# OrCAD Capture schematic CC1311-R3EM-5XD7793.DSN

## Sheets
1 CC1311-R3EM-5XD7793: size A3; title: CC1311-R3EM-5XD7793; rev: A0
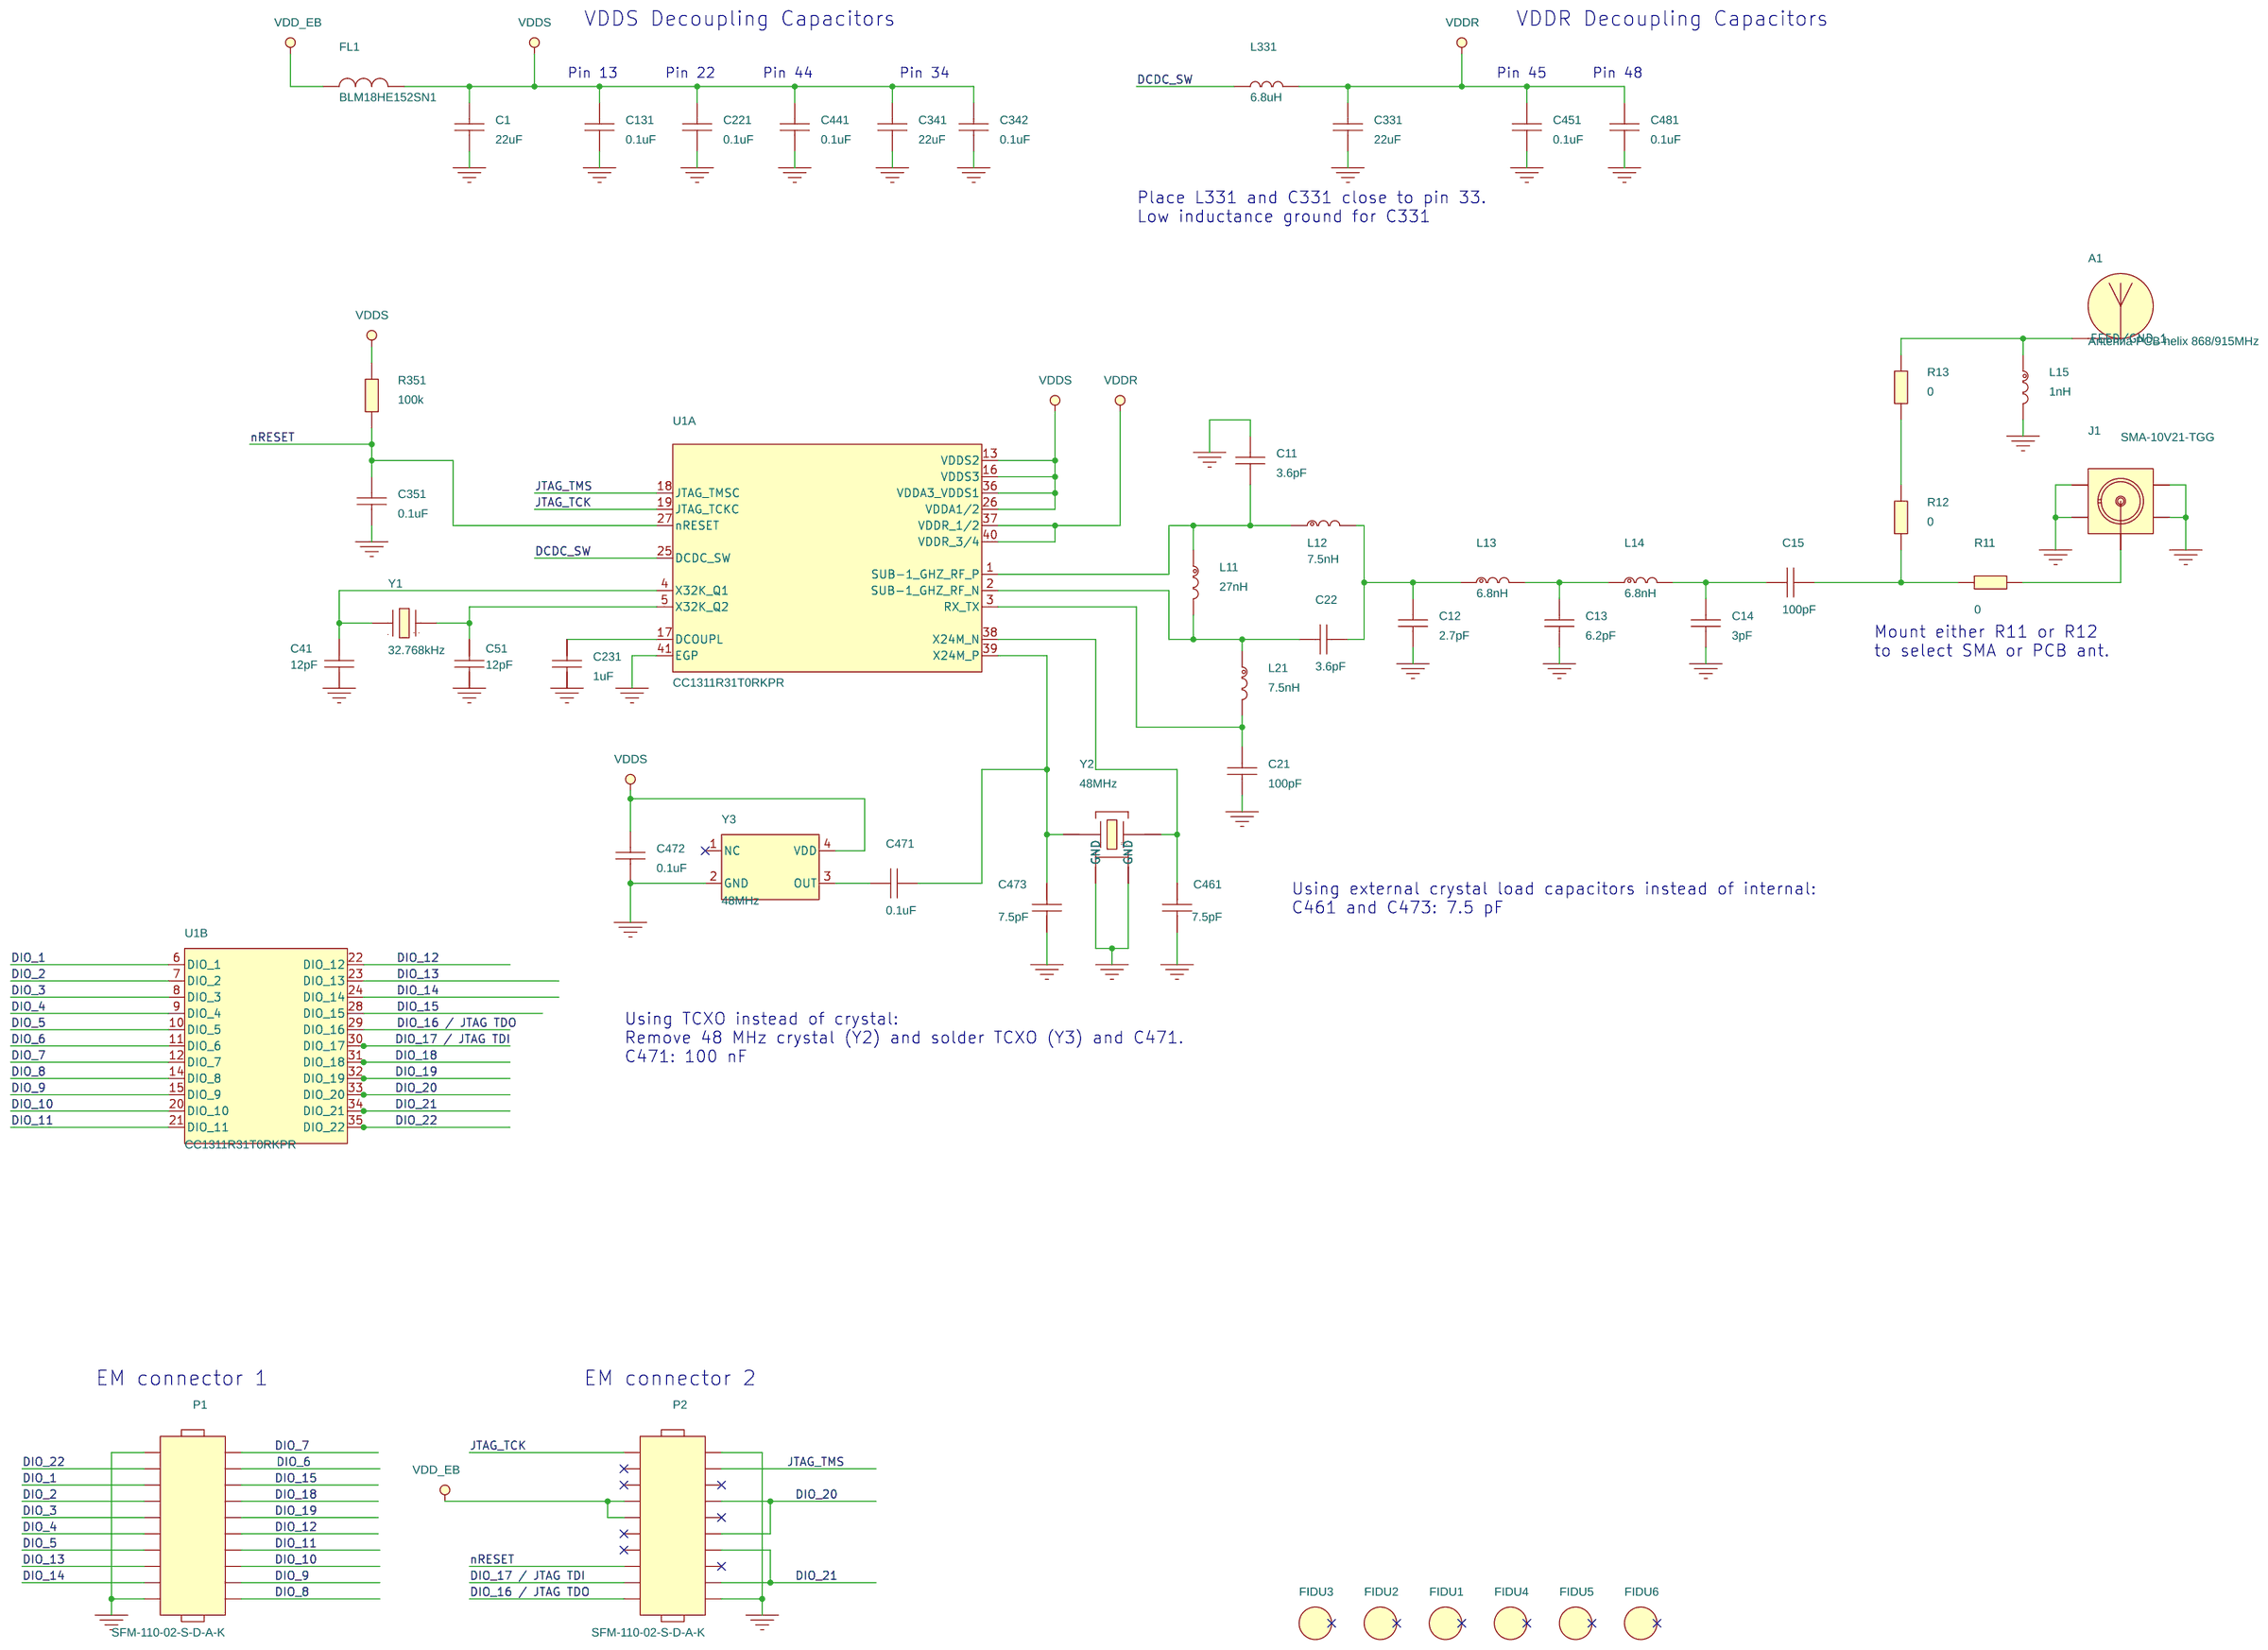
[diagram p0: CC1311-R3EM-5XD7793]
2 Revision
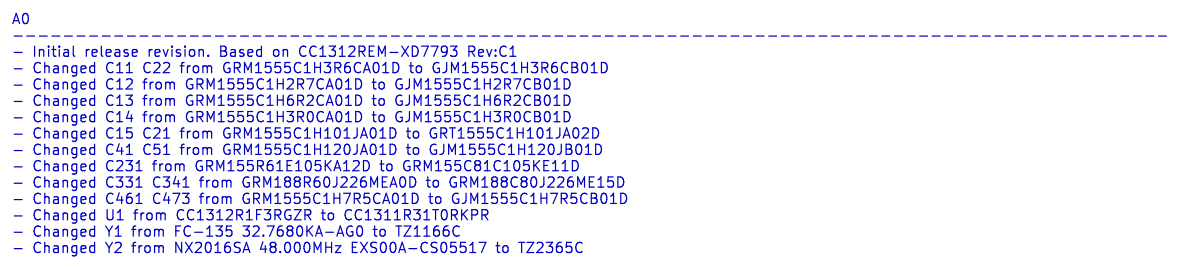
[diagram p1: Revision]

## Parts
A1  Antenna PCB helix 868/915MHz  [Antenna868_915MHz_A2N]
C1  22uF  [CAPC1608X100A2N]
C11  3.6pF  [CAPC1005X60B2N]
C12  2.7pF  [CAPC1005X60B2N]
C13  6.2pF  [CAPC1005X60B2N]
C14  3pF  [CAPC1005X60B2N]
C15  100pF  [CAPC1005X60B2N]
C21  100pF  [CAPC1005X60B2N]
C22  3.6pF  [CAPC1005X60B2N]
C41  12pF  [CAPC1005X60B2N]
C51  12pF  [CAPC1005X60B2N]
C131  0.1uF  [CAPC1005X60B2N]
C221  0.1uF  [CAPC1005X60B2N]
C231  1uF  [CAPC1005X60B2N]
C331  22uF  [CAPC1608X100A2N]
C341  22uF  [CAPC1608X100A2N]
C342  0.1uF  [CAPC1005X60B2N]
C351  0.1uF  [CAPC1005X60B2N]
C441  0.1uF  [CAPC1005X60B2N]
C451  0.1uF  [CAPC1005X60B2N]
C461  7.5pF  [CAPC1005X60B2N]
C471  0.1uF  [CAPC1005X60B2N]
C472  0.1uF  [CAPC1005X60B2N]
C473  7.5pF  [CAPC1005X60B2N]
C481  0.1uF  [CAPC1005X60B2N]
FIDU1  FIDU_1MM  [FID100X115B]
FIDU2  FIDU_1MM  [FID100X115B]
FIDU3  FIDU_1MM  [FID100X115B]
FIDU4  FIDU_1MM  [FID100X115B]
FIDU5  FIDU_1MM  [FID100X115B]
FIDU6  FIDU_1MM  [FID100X115B]
FL1  BLM18HE152SN1  [FIL_BLM18HE152SN1DN]
J1  SMA-10V21-TGG  [HUSTSAN_SMA10V21TGGAN]
L11  27nH  [INDC1005X60D2N]
L12  7.5nH  [INDC1005X60D2N]
L13  6.8nH  [INDC1005X60D2N]
L14  6.8nH  [INDC1005X60D2N]
L15  1nH  [INDC1005X60D2N]
L21  7.5nH  [INDC1005X60D2N]
L331  6.8uH  [INDC2012X150A2N]
P1  SFM-110-02-S-D-A-K  [SAMTEC_SFM11002AN]
P2  SFM-110-02-S-D-A-K  [SAMTEC_SFM11002AN]
R11  0  [RESC1005X40B2N]
R12  0  [RESC1005X40B2N]
R13  0  [RESC1005X40B2N]
R351  100k  [RESC1005X40B2N]
U1  CC1311R31T0RKPR  [QFNFC40P500X500X100-41A2N]  (sections A,B)
Y1  32.768kHz  [XTAL_TZ1166C_B2N]
Y2  48MHz  [OSCCC200X160X50-4A2N]
Y3  48MHz  [OSC_TG2016SBN_A2N]

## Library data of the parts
A1 = ANTENNA: ANTENNA, NON COMPONENT, PCB HELIX 868/915MHz, NOT APPLY; Additional Datasheet URL: N/A; AutoDoc File: http://notefied-dynamic-precision.com/DB/Apps/Desktop/Item/Object.aspx?id=87165; Budget Currency: N/A; Budget Price: N/A; CLASS: DISCRETE; Country of Origin: Missing Info; Datasheet URL: www.ti.com; Datasheet URL 1: N/A; Datasheet URL 2: www.ti.com; Definied Quality: COMMERCIAL; Esd Level: N/A; Exclusive for Customers: TEXAS INSTRUMENTS NORWAY; FPLIST: Antenna868_915MHz_A2N,Antenna868_915MHz_MIRROR_A2N,; LifeCycle Status: ACTIVE; MPN: ANTENNA PCB HELIX 868/915MHz; MPN Status: ACTIVE; MSL: N/A; MTBF: N/A; MTBF Standard: N/A; Manufacturer: TEXAS INSTRUMENTS; Mass: N/A; Max Oper Temp: N/A; Maximum Operating Temperature: N/A; Min Oper Temp: N/A; Minimum Operating Temperature: N/A; Mounting Type: Not Apply; NOTE Status: PREFERRED; NOTEfied URL: https://notefied-dynamic-precision.com/NOTEfiedWebInterface/part/show?partNumber=13-00397; Notes: Custom Item; Old Footprint: Antenna868_915MHz_A2N,Antenna868_915MHz_MIRROR_A2N; Packing Size: 2500; Packing Type: Tape & Reel; Part Number: 13-00397; Part Type: Mechanic|ANTENNA|NON COMPONENT; REACH/SVHC Compliance: Missing Info; REACH/SVHC Details: N/A; REACH/SVHC Source: N/A; REACH/SVHC Status: Missing Info; ROHS: Compliant; Revision: R019; RoHS Status: ROHS_COMPLIANT; Status: Released; Texas Part Status: Under Review; Type: Mechanic; Vendor: TEXAS INSTRUMENTS; Vendor Part Number: ANTENNA PCB HELIX 868/915MHz; Vendor Part Status: Active; WEIGHT: N/A
C1 = CAPACITOR: CAPACITOR, CERAMIC X6S, 22uF, 6.3V, -20%/+20%, -55DEGC/+105DEGC, 0603, SMD; ALT_SYMBOLS: CAPC1608X100A2L,CAPC1608X100A2M; Additional Datasheet URL: https://search.murata.co.jp/Ceramy/image/img/A01X/G101/ENG/GRM188C80J226ME15-02A.pdf; Budgetary Price: 0.07648 USD; CLASS: DISCRETE; Datasheet URL: https://www.murata.com/-/media/webrenewal/support/library/catalog/products/capacitor/mlcc/c02e.ashx; Dielectric Type: X6S; Lead Time: 15; Mass: 0.0091g; Maximum Operating Temperature: +105DEGC; Maximum Tolerance: +20%; Minimum Operating Temperature: -55DEGC; Minimum Tolerance: -20%; Mounting Type: SMD; NOTEfied URL: https://notefied-dynamic-precision.com/NOTEfiedWebInterface/part/show?partNumber=02-09737; PCB Package: 0603; Packing Size: 4000; Packing Type: Tape & Reel; Part Number: 02-09737; Part Type: Capacitor|CERAMIC|0603|STANDARD; REACH/SVHC Compliance: Compliant; REACH/SVHC Details: SVHC List Version Jan 16, 2020; REACH/SVHC Source: REACH Declaration; REACH/SVHC Status: Unaffected; ROHS: Compliant; Rated Current: N/A; Rated Voltage: 6.3V; Revision: R002; Status: Released; Texas Part Status: Under Review; Type: Capacitor; Vendor: MURATA; Vendor Part Number: GRM188C80J226ME15D; Vendor Part Status: Active
C11 C22 = CAPACITOR: CAPACITOR, CERAMIC C0G/NP0, 3.6pF, 50V, -0.25pF/+0.25pF, -55DEGC/+125DEGC, 0402, SMD; Additional Datasheet URL: https://search.murata.co.jp/Ceramy/image/img/A01X/G101/ENG/GJM1555C1H3R6CB01-01.pdf; Datasheet URL: https://www.murata.com/-/media/webrenewal/support/library/catalog/products/capacitor/mlcc/c02e.ashx; Dielectric Type: C0G/NP0; Mass: 0.0016g; Maximum Operating Temperature: +125DEGC; Maximum Tolerance: +0.25pF; Minimum Operating Temperature: -55DEGC; Minimum Tolerance: -0.25pF; Mounting Type: SMD; NOTEfied URL: https://notefied-dynamic-precision.com/NOTEfiedWebInterface/part/show?partNumber=02-09714; PCB Package: 0402; Packing Size: 10000; Packing Type: Tape & Reel; Part Number: 02-09714; Part Type: Capacitor|CERAMIC|0402|STANDARD; REACH/SVHC Compliance: Compliant; REACH/SVHC Details: SVHC List Version Jan 16, 2020; REACH/SVHC Source: REACH Declaration; REACH/SVHC Status: Unaffected; ROHS: Compliant; Rated Voltage: 50V; Revision: R003; Status: Released; Texas Part Status: Under Review; Type: Capacitor; Vendor: MURATA; Vendor Part Number: GJM1555C1H3R6CB01D; Vendor Part Status: Active
C12 = CAPACITOR: CAPACITOR, CERAMIC C0G/NP0, 2.7pF, 50V, -0.25pF/+0.25pF, -55DEGC/+125DEGC, 0402, SMD; Additional Datasheet URL: https://search.murata.co.jp/Ceramy/image/img/A01X/G101/ENG/GJM1555C1H2R7CB01-01.pdf; Datasheet URL: https://www.murata.com/-/media/webrenewal/support/library/catalog/products/capacitor/mlcc/c02e.ashx; Dielectric Type: C0G/NP0; Mass: 0.0016g; Maximum Operating Temperature: +125DEGC; Maximum Tolerance: +0.25pF; Minimum Operating Temperature: -55DEGC; Minimum Tolerance: -0.25pF; Mounting Type: SMD; NOTEfied URL: https://notefied-dynamic-precision.com/NOTEfiedWebInterface/part/show?partNumber=02-09712; PCB Package: 0402; Packing Size: 10000; Packing Type: Tape & Reel; Part Number: 02-09712; Part Type: Capacitor|CERAMIC|0402|STANDARD; REACH/SVHC Compliance: Compliant; REACH/SVHC Details: SVHC List Version Jan 16, 2020; REACH/SVHC Source: REACH Declaration; REACH/SVHC Status: Unaffected; ROHS: Compliant; Rated Voltage: 50V; Revision: R003; Status: Released; Texas Part Status: Under Review; Type: Capacitor; Vendor: MURATA; Vendor Part Number: GJM1555C1H2R7CB01D; Vendor Part Status: Active
C13 = CAPACITOR: CAPACITOR, CERAMIC C0G/NP0, 6.2pF, 50V, -0.25pF/+0.25pF, -55DEGC/+125DEGC, 0402, SMD; Additional Datasheet URL: https://search.murata.co.jp/Ceramy/image/img/A01X/G101/ENG/GJM1555C1H6R2CB01-01.pdf; Datasheet URL: https://www.murata.com/-/media/webrenewal/support/library/catalog/products/capacitor/mlcc/c02e.ashx; Dielectric Type: C0G/NP0; Mass: 0.0016g; Maximum Operating Temperature: +125DEGC; Maximum Tolerance: +0.25pF; Minimum Operating Temperature: -55DEGC; Minimum Tolerance: -0.25pF; Mounting Type: SMD; NOTEfied URL: https://notefied-dynamic-precision.com/NOTEfiedWebInterface/part/show?partNumber=02-09717; PCB Package: 0402; Packing Size: 10000; Packing Type: Tape & Reel; Part Number: 02-09717; Part Type: Capacitor|CERAMIC|0402|STANDARD; REACH/SVHC Compliance: Compliant; REACH/SVHC Details: SVHC List Version Jan 16, 2020; REACH/SVHC Source: REACH Declaration; REACH/SVHC Status: Unaffected; ROHS: Compliant; Rated Voltage: 50V; Revision: R003; Status: Released; Texas Part Status: Under Review; Type: Capacitor; Vendor: MURATA; Vendor Part Number: GJM1555C1H6R2CB01D; Vendor Part Status: Active
C14 = CAPACITOR: CAPACITOR, CERAMIC C0G/NP0, 3pF, 50V, -0.25pF/+0.25pF, -55DEGC/+125DEGC, 0402, SMD; Additional Datasheet URL: https://search.murata.co.jp/Ceramy/image/img/A01X/G101/ENG/GJM1555C1H3R0CB01-01.pdf; Datasheet URL: https://www.murata.com/-/media/webrenewal/support/library/catalog/products/capacitor/mlcc/c02e.ashx; Dielectric Type: C0G/NP0; Mass: 0.0016g; Maximum Operating Temperature: +125DEGC; Maximum Tolerance: +0.25pF; Minimum Operating Temperature: -55DEGC; Minimum Tolerance: -0.25pF; Mounting Type: SMD; NOTEfied URL: https://notefied-dynamic-precision.com/NOTEfiedWebInterface/part/show?partNumber=02-09713; PCB Package: 0402; Packing Size: 10000; Packing Type: Tape & Reel; Part Number: 02-09713; Part Type: Capacitor|CERAMIC|0402|STANDARD; REACH/SVHC Compliance: Compliant; REACH/SVHC Details: SVHC List Version Jan 16, 2020; REACH/SVHC Source: REACH Declaration; REACH/SVHC Status: Unaffected; ROHS: Compliant; Rated Voltage: 50V; Revision: R003; Status: Released; Texas Part Status: Under Review; Type: Capacitor; Vendor: MURATA; Vendor Part Number: GJM1555C1H3R0CB01D; Vendor Part Status: Active
C15 C21 = CAPACITOR: CAPACITOR, CERAMIC C0G/NP0, 100pF, 50V, -5%/+5%, -55DEGC/+125DEGC, 0402, SMD; Additional Datasheet URL: https://search.murata.co.jp/Ceramy/image/img/A01X/G101/ENG/GRT1555C1H101JA02-01.pdf; Budgetary Price: 0.023 EUR; Datasheet URL: https://www.murata.com/-/media/webrenewal/support/library/catalog/products/capacitor/mlcc/c02e.ashx?la=en-gb; Dielectric Type: C0G/NP0; Lead Time: 19; Mass: 0.0016g; Maximum Operating Temperature: +125DEGC; Maximum Tolerance: +5%; Minimum Operating Temperature: -55DEGC; Minimum Tolerance: -5%; Mounting Type: SMD; NOTEfied URL: https://notefied-dynamic-precision.com/NOTEfiedWebInterface/part/show?partNumber=02-09727; PCB Package: 0402; Packing Size: 10000; Packing Type: Tape & Reel; Part Number: 02-09727; Part Type: Capacitor|CERAMIC|0402|STANDARD; REACH/SVHC Compliance: Compliant; REACH/SVHC Details: SVHC List Version Jan 16, 2020; REACH/SVHC Source: REACH Declaration; REACH/SVHC Status: Unaffected; ROHS: Compliant; Rated Voltage: 50V; Revision: R003; Status: Released; Texas Part Status: Under Review; Type: Capacitor; Vendor: MURATA; Vendor Part Number: GRT1555C1H101JA02D; Vendor Part Status: Active
C41 C51 = CAPACITOR: CAPACITOR, CERAMIC C0G/NP0, 12pF, 50V, -5%/+5%, -55DEGC/+125DEGC, 0402, SMD; Additional Datasheet URL: https://search.murata.co.jp/Ceramy/image/img/A01X/G101/ENG/GJM1555C1H120JB01-01.pdf; AutoDoc File: http://notefied-dynamic-precision.com/DB/Apps/Desktop/Item/Object.aspx?id=84867; Budget Currency: EUR; Budget Price: 0.006; Datasheet URL: https://www.murata.com/-/media/webrenewal/support/library/catalog/products/capacitor/mlcc/c02e.ashx; Datasheet URL 1: http://search.murata.co.jp/Ceramy/image/img/w_hinm/L0005E.pdf; Datasheet URL 2: http://psearch.murata.com/capacitor/product/GRM1555C1H120JA01%23.pdf; Definied Quality: INDUSTRIAL; Dielectric Type: C0G/NP0; Esd Level: N/A; MPN: GRM1555C1H120JA01D; MPN Status: ACTIVE; MSL: 1; MTBF: N/A; MTBF Standard: N/A; Manufacturer: MURATA; Mass: 0.0016g; Max Oper Temp: +125DEGC; Max TC: +30PPM/DEGC; Max Tol: +5%; Maximum Operating Temperature: +125DEGC; Maximum Tolerance: +5%; Min Oper Temp: -55DEGC; Min TC: -30PPM/DEGC; Min Tol: -5%; Minimum Operating Temperature: -55DEGC; Minimum Tolerance: -5%; Mounting Type: SMD; NOTE Status: PREFERRED; NOTEfied URL: https://notefied-dynamic-precision.com/NOTEfiedWebInterface/part/show?partNumber=02-09704; Old Footprint: CAPC1005X60N; PCB Package: 0402; Packing Size: 10000; Packing Type: Tape & Reel; Part Number: 02-09704; Part Type: Capacitor|CERAMIC|0402|STANDARD; REACH/SVHC Compliance: Compliant; REACH/SVHC Details: SVHC List Version Jan 16, 2020; REACH/SVHC Source: REACH Declaration; REACH/SVHC Status: Unaffected; ROHS: Compliant; Rated Voltage: 50V; Revision: R003; RoHS Status: ROHS_COMPLIANT; Rtd Voltage: 50V; Status: Released; Texas Part Status: Under Review; Type: Capacitor; Vendor: MURATA; Vendor Part Number: GJM1555C1H120JB01D; Vendor Part Status: Active; WEIGHT: 0.0016g
C131 C221 C342 C351 C441 C451 C471 C472 C481 = CAPACITOR: CAPACITOR, CERAMIC X7R, 0.1uF, 25V, -10%/+10%, -55DEGC/+125DEGC, 0402, SMD; Additional Datasheet URL: https://search.murata.co.jp/Ceramy/image/img/A01X/G101/ENG/GRM155R71E104KE14-01A.pdf; CLASS: DISCRETE; Datasheet URL: https://www.murata.com/~/media/webrenewal/support/library/catalog/products/capacitor/mlcc/c02e.ashx?la=en-gb; Dielectric Type: X7R; Mass: 0.0016g; Maximum Operating Temperature: +125DEGC; Maximum Tolerance: +10%; Minimum Operating Temperature: -55DEGC; Minimum Tolerance: -10%; Mounting Type: SMD; NOTEfied URL: https://notefied-dynamic-precision.com/NOTEfiedWebInterface/part/show?partNumber=02-07861; PCB Package: 0402; Packing Size: 10000; Packing Type: Tape & Reel; Part Number: 02-07861; Part Type: Capacitor|CERAMIC|0402|STANDARD; REACH/SVHC Compliance: Compliant; REACH/SVHC Details: SVHC List Version Jul 7, 2017; REACH/SVHC Source: REACH Declaration; REACH/SVHC Status: Unaffected; ROHS: Compliant; Rated Voltage: 25V; Revision: R014; Status: Released; Texas Part Status: Under Review; Type: Capacitor; Vendor: MURATA; Vendor Part Number: GRM155R71E104KE14D; Vendor Part Status: NRND
C231 = CAPACITOR: CAPACITOR, CERAMIC X6S, 1uF, 16V, -10%/+10%, -55DEGC/+105DEGC, 0402, SMD; Additional Datasheet URL: https://search.murata.co.jp/Ceramy/image/img/A01X/G101/ENG/GRM155C81C105KE11-01A.pdf; Datasheet URL: https://www.murata.com/-/media/webrenewal/support/library/catalog/products/capacitor/mlcc/c02e.ashx; Dielectric Type: X6S; Mass: 0.0016g; Maximum Operating Temperature: +105DEGC; Maximum Tolerance: +10%; Minimum Operating Temperature: -55DEGC; Minimum Tolerance: -10%; Mounting Type: SMD; NOTEfied URL: https://notefied-dynamic-precision.com/NOTEfiedWebInterface/part/show?partNumber=02-09724; PCB Package: 0402; Packing Size: 10000; Packing Type: Tape & Reel; Part Number: 02-09724; Part Type: Capacitor|CERAMIC|0402|STANDARD; REACH/SVHC Compliance: Compliant; REACH/SVHC Details: SVHC List Version Jan 16, 2020; REACH/SVHC Source: REACH Declaration; REACH/SVHC Status: Unaffected; ROHS: Compliant; Rated Voltage: 16V; Revision: R003; Status: Released; Texas Part Status: Under Review; Type: Capacitor; Vendor: MURATA; Vendor Part Number: GRM155C81C105KE11D; Vendor Part Status: Active
C331 C341 = CAPACITOR: CAPACITOR, CERAMIC X6S, 22uF, 6.3V, -20%/+20%, -55DEGC/+105DEGC, 0603, SMD; ALT_SYMBOLS: CAPC1608X100A2L,CAPC1608X100A2M; Additional Datasheet URL: https://search.murata.co.jp/Ceramy/image/img/A01X/G101/ENG/GRM188C80J226ME15-02A.pdf; Budgetary Price: 0.07648 USD; Datasheet URL: https://www.murata.com/-/media/webrenewal/support/library/catalog/products/capacitor/mlcc/c02e.ashx; Dielectric Type: X6S; Lead Time: 15; Mass: 0.0091g; Maximum Operating Temperature: +105DEGC; Maximum Tolerance: +20%; Minimum Operating Temperature: -55DEGC; Minimum Tolerance: -20%; Mounting Type: SMD; NOTEfied URL: https://notefied-dynamic-precision.com/NOTEfiedWebInterface/part/show?partNumber=02-09737; PCB Package: 0603; Packing Size: 4000; Packing Type: Tape & Reel; Part Number: 02-09737; Part Type: Capacitor|CERAMIC|0603|STANDARD; REACH/SVHC Compliance: Compliant; REACH/SVHC Details: SVHC List Version Jan 16, 2020; REACH/SVHC Source: REACH Declaration; REACH/SVHC Status: Unaffected; ROHS: Compliant; Rated Current: N/A; Rated Voltage: 6.3V; Revision: R002; Status: Released; Texas Part Status: Under Review; Type: Capacitor; Vendor: MURATA; Vendor Part Number: GRM188C80J226ME15D; Vendor Part Status: Active
C461 C473 = CAPACITOR: CAPACITOR, CERAMIC C0G/NP0, 7.5pF, 50V, -0.25pF/+0.25pF, -55DEGC/+125DEGC, 0402, SMD; Additional Datasheet URL: https://search.murata.co.jp/Ceramy/image/img/A01X/G101/ENG/GJM1555C1H7R5CB01-01.pdf; Datasheet URL: https://www.murata.com/-/media/webrenewal/support/library/catalog/products/capacitor/mlcc/c02e.ashx; Dielectric Type: C0G/NP0; Mass: 0.0016g; Maximum Operating Temperature: +125DEGC; Maximum Tolerance: +0.25pF; Minimum Operating Temperature: -55DEGC; Minimum Tolerance: -0.25pF; Mounting Type: SMD; NOTEfied URL: https://notefied-dynamic-precision.com/NOTEfiedWebInterface/part/show?partNumber=02-09718; PCB Package: 0402; Packing Size: 10000; Packing Type: Tape & Reel; Part Number: 02-09718; Part Type: Capacitor|CERAMIC|0402|STANDARD; REACH/SVHC Compliance: Compliant; REACH/SVHC Details: SVHC List Version Jan 16, 2020; REACH/SVHC Source: REACH Declaration; REACH/SVHC Status: Unaffected; ROHS: Compliant; Rated Voltage: 50V; Revision: R003; Status: Released; Texas Part Status: Under Review; Type: Capacitor; Vendor: MURATA; Vendor Part Number: GJM1555C1H7R5CB01D; Vendor Part Status: Active
FIDU1-FIDU6 = FIDMARK: NON COMPONENT, FIDUCIAL MARK, ROUND 1mm, SMD; Additional Datasheet URL: N/A; AutoDoc File: http://notefied-dynamic-precision.com/DB/Apps/Desktop/Item/Object.aspx?id=74548; CLASS: IO; Country of Origin: Missing Info; Datasheet URL: N/A; Mass: N/A; Mounting Type: SMD; NOTEfied URL: https://notefied-dynamic-precision.com/NOTEfiedWebInterface/part/show?partNumber=19-00111; Old Footprint: FID100X115; Packing Size: N/A; Packing Type: Missing Info; Part Number: 19-00111; Part Type: Non Component|FIDUCIAL; ROHS: Compliant; Revision: R015; Status: Released; Type: Non Component; Vendor: NON_COMPONENT; Vendor Part Number: FIDUCIAL_1mm; Vendor Part Status: Active
FL1 = FILTER_2PIN: FILTER, EMI, FERRITE BEAD, 1500@100MHz, -25%/+25%, -55DEGC/+125DEGC, 0603, SMD; ALT_SYMBOLS: FIL_BLM18HE152SN1DL,FIL_BLM18HE152SN1DM; Additional Datasheet URL: https://www.murata.com/en-eu/products/productdata/8796741599262/ENFA0004.pdf?1441769419000; Budgetary Price: 0.065 EUR; Country of Origin: Japan,Singapore,Thailand; Datasheet URL: https://www.murata.com/~/media/webrenewal/support/library/catalog/products/emc/emifil/c31e.ashx; Frequency: 100MHz; Impedance: 1500; Inductance: N/A; Lead Time: 9; Mass: 0.006g; Maximum Operating Temperature: +125DEGC; Maximum Tolerance: +25%; Minimum Operating Temperature: -55DEGC; Minimum Tolerance: -25%; Mounting Type: SMD; NOTEfied URL: https://notefied-dynamic-precision.com/NOTEfiedWebInterface/part/show?partNumber=04-00470; PCB Package: 0603; Packing Size: 4000; Packing Type: Tape & Reel; Part Number: 04-00470; Part Type: Filter|EMI|FERRITE BEAD|0603; REACH/SVHC Compliance: Compliant; REACH/SVHC Details: SVHC List Version Jul 7, 2017; REACH/SVHC Source: REACH Declaration; REACH/SVHC Status: Unaffected; ROHS: Compliant; Rated Current: 0.5A; Rated Voltage: N/A; Revision: R015; Status: Released; Texas Part Status: Under Review; Type: Filter; Vendor: MURATA; Vendor Part Number: BLM18HE152SN1D; Vendor Part Status: Active
J1 = CONN_COAX_1+4: CONNECTOR, COAX, RF, FEMALE, STRAIGHT, 1 PIN, SMD; ALT_SYMBOLS: HUSTSAN_SMA10V21TGGL,HUSTSAN_SMA10V21TGGM; Additional Datasheet URL: http://www.hustsan.com.tw/cgi-bin/productfn/pdt_detail_lst.pl?ProdID=143; AutoDoc File: http://notefied-dynamic-precision.com/DB/Apps/Desktop/Item/Object.aspx?id=84956; Budget Currency: USD; Budget Price: 1.21; CLASS: IO; Country of Origin: Taiwan; Datasheet URL: http://www.hustsan.com.tw/uploaddir/product/SMA-10V21.pdf; Datasheet URL 1: http://www.hustsan.com.tw/uploaddir/product/SMA-10V21.pdf; Datasheet URL 2: http://www.hustsan.com.tw/uploaddir/product/SMA-10V21.pdf; FPLIST: HUSTSAN_SMA10V21TGGAN,HUSTSAN_SMA10V21TGGN; MPN Status: ACTIVE; MSL: N/A; Manufacturer: HUS-TSAN; Mass: N/A; Mounting Type: SMD; NOTE Status: PREFERRED; NOTEfied URL: https://notefied-dynamic-precision.com/NOTEfiedWebInterface/part/show?partNumber=06-02188; No Of Pos: 1; Number of Positions: 1; Old Footprint: HUSTSAN_SMA10V21TGGAN,HUSTSAN_SMA10V21TGGN; Packing Size: 350; Packing Type: Tape & Reel; Part Number: 06-02188; Part Type: Connector|COAX|RF; REACH/SVHC Compliance: Compliant; REACH/SVHC Details: SVHC List Version Jun 20, 2016; REACH/SVHC Source: REACH Declaration; REACH/SVHC Status: Unaffected; ROHS: Compliant; Revision: R014; RoHS Status: N/A; Status: Released; Texas Part Status: Under Review; Type: Connector; Vendor: HUS-TSAN; Vendor Part Status: Active; WEIGHT: N/A
L11 = INDUCTOR_HOR_1_2: INDUCTOR, RF, CHIP, NON-MAGNETIC CORE, 27nH, -5%/+5%, 0.3A, -55DEGC/+125DEGC, 0402, SMD; Additional Datasheet URL: https://search.murata.co.jp/Ceramy/image/img/P02/JELF243B-0010.pdf; Budgetary Price: 0.03 EUR; Country of Origin: Japan,Singapore; Datasheet URL: https://www.murata.com/~/media/webrenewal/support/library/catalog/products/inductor/chip/o05e.ashx?la=en-gb; Exclusive for Customers: TEXAS INSTRUMENTS NORWAY; Frequency: 1700MHz; Lead Time: 9; Mass: 0.001g; Maximum Operating Temperature: +125DEGC; Maximum Tolerance: +5%; Minimum Operating Temperature: -55DEGC; Minimum Tolerance: -5%; Mounting Type: SMD; NOTEfied URL: https://notefied-dynamic-precision.com/NOTEfiedWebInterface/part/show?partNumber=03-07528; Notes: Standard item: Duplicate Reason: custom footprint for TEXAS INSTRUMENTS NORWAY.; PCB Package: 0402; Packing Size: 10000; Packing Type: Tape & Reel; Part Number: 03-07528; Part Type: Inductor|RF|CHIP|0402; REACH/SVHC Compliance: Compliant; REACH/SVHC Details: SVHC List Version Jul 7, 2017; REACH/SVHC Source: REACH Declaration; REACH/SVHC Status: Unaffected; ROHS: Compliant; Resistance: 0.46; Revision: R018; Status: Released; Texas Part Status: Under Review; Type: Inductor; Vendor: MURATA; Vendor Part Number: LQG15HS27NJ02D; Vendor Part Status: Active
L12 L21 = INDUCTOR_HOR_1_2: INDUCTOR, RF, CHIP, NON-MAGNETIC CORE, 7.5nH, -5%/+5%, 0.3A, -55DEGC/+125DEGC, 0402, SMD; Additional Datasheet URL: https://search.murata.co.jp/Ceramy/image/img/P02/JELF243B-0010.pdf; Budgetary Price: 0.03 EUR; Country of Origin: Missing Info; Datasheet URL: https://www.murata.com/~/media/webrenewal/support/library/catalog/products/inductor/chip/o05e.ashx?la=en-gb; Frequency: 4.2GHz; Lead Time: 10; Mass: 0.001g; Maximum Operating Temperature: +125DEGC; Maximum Tolerance: +5%; Minimum Operating Temperature: -55DEGC; Minimum Tolerance: -5%; Mounting Type: SMD; NOTEfied URL: https://notefied-dynamic-precision.com/NOTEfiedWebInterface/part/show?partNumber=03-07022; PCB Package: 0402; Packing Size: 10000; Packing Type: Tape & Reel; Part Number: 03-07022; Part Type: Inductor|RF|CHIP|0402; REACH/SVHC Compliance: Compliant; REACH/SVHC Details: SVHC List Version Jul 7, 2017; REACH/SVHC Source: REACH Declaration; REACH/SVHC Status: Unaffected; ROHS: Compliant; Resistance: 0.24; Revision: R017; Status: Released; Texas Part Status: Under Review; Type: Inductor; Vendor: MURATA; Vendor Part Number: LQG15HS7N5J02D; Vendor Part Status: Active
L13 L14 = INDUCTOR_HOR_1_2: INDUCTOR, RF, CHIP, NON-MAGNETIC CORE, 6.8nH, -5%/+5%, 0.3A, -55DEGC/+125DEGC, 0402, SMD; Additional Datasheet URL: https://search.murata.co.jp/Ceramy/image/img/P02/JELF243B-0010.pdf; Budgetary Price: 0.03 EUR; Country of Origin: Japan,Singapore; Datasheet URL: https://www.murata.com/~/media/webrenewal/support/library/catalog/products/inductor/chip/o05e.ashx?la=en-gb; Exclusive for Customers: TEXAS INSTRUMENTS NORWAY; Frequency: 4.5GHz; Lead Time: 9; Mass: 0.001g; Maximum Operating Temperature: +125DEGC; Maximum Tolerance: +5%; Minimum Operating Temperature: -55DEGC; Minimum Tolerance: -5%; Mounting Type: SMD; NOTEfied URL: https://notefied-dynamic-precision.com/NOTEfiedWebInterface/part/show?partNumber=03-07532; Notes: Standard item: Duplicate Reason: custom footprint for TEXAS INSTRUMENTS NORWAY.; PCB Package: 0402; Packing Size: 10000; Packing Type: Tape & Reel; Part Number: 03-07532; Part Type: Inductor|RF|CHIP|0402; REACH/SVHC Compliance: Compliant; REACH/SVHC Details: SVHC List Version Jul 7, 2017; REACH/SVHC Source: REACH Declaration; REACH/SVHC Status: Unaffected; ROHS: Compliant; Resistance: 0.24; Revision: R018; Status: Released; Texas Part Status: Under Review; Type: Inductor; Vendor: MURATA; Vendor Part Number: LQG15HS6N8J02D; Vendor Part Status: Active
L15 = INDUCTOR_HOR_1_2: INDUCTOR, RF, CHIP, NON-MAGNETIC CORE, 1nH, -0.3nH/+0.3nH, 0.3A, -55DEGC/+125DEGC, 0402, SMD; ALT_SYMBOLS: INDC1005X60C2L,INDC1005X60C2M; Additional Datasheet URL: https://search.murata.co.jp/Ceramy/image/img/P02/JELF243B-0010.pdf; Budgetary Price: 0.031 EUR; Country of Origin: Japan,Singapore; Datasheet URL: https://www.murata.com/~/media/webrenewal/support/library/catalog/products/inductor/chip/o05e.ashx?la=en-gb; Frequency: 10GHz; Lead Time: 9; Mass: 0.001g; Maximum Operating Temperature: +125DEGC; Maximum Tolerance: +0.3nH; Minimum Operating Temperature: -55DEGC; Minimum Tolerance: -0.3nH; Mounting Type: SMD; NOTEfied URL: https://notefied-dynamic-precision.com/NOTEfiedWebInterface/part/show?partNumber=03-06607; PCB Package: 0402; Packing Size: 10000; Packing Type: Tape & Reel; Part Number: 03-06607; Part Type: Inductor|RF|CHIP|0402; REACH/SVHC Compliance: Compliant; REACH/SVHC Details: SVHC List Version Jul 7, 2017; REACH/SVHC Source: REACH Declaration; REACH/SVHC Status: Unaffected; ROHS: Compliant; Resistance: 0.07; Revision: R016; Status: Released; Texas Part Status: Under Review; Type: Inductor; Vendor: MURATA; Vendor Part Number: LQG15HS1N0S02D; Vendor Part Status: Active
L331 = INDUCTOR: INDUCTOR, STANDARD, FERRITE CORE, 6.8uH, -20%/+20%, 0.11A, -55DEGC/+125DEGC, 0805, SMD; ALT_SYMBOLS: INDC2012X150A2L,INDC2012X150A2M; Additional Datasheet URL: https://product.tdk.com/en/search/inductor/inductor/smd/info?part_no=MLZ2012N6R8LT000; Budgetary Price: 0.045 USD; Country of Origin: Missing Info; Datasheet URL: http://product.tdk.com/info/en/catalog/datasheets/inductor_commercial_decoupling_mlz2012_en.pdf; Lead Time: 10; Mass: 0.01g; Maximum Operating Temperature: +125DEGC; Maximum Tolerance: +20%; Minimum Operating Temperature: -55DEGC; Minimum Tolerance: -20%; Mounting Type: SMD; NOTEfied URL: https://notefied-dynamic-precision.com/NOTEfiedWebInterface/part/show?partNumber=03-07266; PCB Package: 0805; Packing Size: 4000; Packing Type: Tape & Reel; Part Number: 03-07266; Part Type: Inductor|STANDARD|CHIP|0805; REACH/SVHC Compliance: Compliant; REACH/SVHC Details: SVHC List Version Jan 12, 2017; REACH/SVHC Source: REACH Declaration; REACH/SVHC Status: Unaffected; ROHS: Compliant; Resistance: 0.25; Revision: R014; Status: Released; Texas Part Status: Under Review; Type: Inductor; Vendor: TDK; Vendor Part Number: MLZ2012N6R8LT000; Vendor Part Status: Active
P1 P2 = CONN_HEADER_2X10_P_S: CONNECTOR, HEADER, FEMALE, STRAIGHT, 2 ROWS, 20 PINS, PITCH 1.27mm, SMD; ALT_SYMBOLS: SAMTEC_SFM11002AL,SAMTEC_SFM11002AM; Additional Datasheet URL: http://suddendocs.samtec.com/prints/sfm-1xx-xx-xxx-d-xxx-mkt.pdf; Alt IPC Footprints: SAMTEC_SFM11002AL,SAMTEC_SFM11002AM; AutoDoc File: https://notefied-dynamic-precision.com/NotefiedWebServices/AutoDocs.aspx?itemid=85603; Budgetary Price: 5.3504 USD; CLASS: IO; Country of Origin: China,Costa Rica,Malaysia,Singapore,United States; Datasheet URL: http://suddendocs.samtec.com/catalog_english/sfm.pdf; Datasheet URL 1: http://www.samtec.com/ProductInformation/TechnicalSpecifications/CatalogPages.aspx?series=SFM; Datasheet URL 2: http://www.samtec.com/documents/webfiles/cpdf/SFM-1XX-XX-XX-S-XX-MKT1.pdf; Lead Time: 4; MPN: SFM-110-02-SM-D-A-K-TR; MPN Status: ACTIVE; Manufacturer: SAMTEC; Mass: 0.30875g; Max Oper Temp: +125DEGC; Maximum Operating Temperature: +125DEGC; Min Oper Temp: -55DEGC; Minimum Operating Temperature: -55DEGC; Mounting Type: SMD; NOTE Status: PREFERRED; NOTEfied URL: https://notefied-dynamic-precision.com/NOTEfiedWebInterface/part/show?partNumber=06-02251; No Of Pos: 20; No Of Rows: 2; Number of Positions: 20; Number of Rows: 2; Packing Size: 725; Packing Type: Tape & Reel; Part Number: 06-02251; Part Type: Connector|HEADER|STANDARD; Pitch: 1.27mm; REACH/SVHC Compliance: Compliant; REACH/SVHC Details: SVHC List Version Jan 12, 2017; REACH/SVHC Source: Material Declaration; REACH/SVHC Status: Unaffected; ROHS: Compliant; Revision: R013; RoHS Status: ROHS_COMPLIANT; Status: Released; Texas Part Status: Under Review; Type: Connector; Vendor: SAMTEC; Vendor Part Number: SFM-110-02-SM-D-A-K-TR; Vendor Part Status: Active
R11-R13 = RESISTOR: RESISTOR, THICK FILM, 0, 0R/+0.02R, 0.063W, 1.5A, -55DEGC/+155DEGC, 0402, SMD; Additional Datasheet URL: N/A; Budgetary Price: 0.007 EUR; Country of Origin: Israel; Datasheet URL: http://www.vishay.com/docs/20035/dcrcwe3.pdf; Exclusive for Customers: TEXAS INSTRUMENTS NORWAY; Lead Time: 14; Mass: 0.0006152g; Maximum Operating Temperature: +155DEGC; Maximum Temperature Coefficient: N/A; Maximum Tolerance: +0.02R; Minimum Operating Temperature: -55DEGC; Minimum Temperature Coeficient: N/A; Minimum Tolerance: 0R; Mounting Type: SMD; NOTEfied URL: https://notefied-dynamic-precision.com/NOTEfiedWebInterface/part/show?partNumber=01-22495; Notes: Standard item: Duplicate Reason: custom footprint for TEXAS INSTRUMENTS NORWAY.; PCB Package: 0402; Packing Size: 10000; Packing Type: Tape & Reel; Part Number: 01-22495; Part Type: Resistor|0402|JUMPER; REACH/SVHC Compliance: Compliant; REACH/SVHC Details: SVHC List Version Jul 07, 2017; REACH/SVHC Source: REACH Declaration; REACH/SVHC Status: Unaffected; ROHS: Exempt; Rated Current: 1.5A; Rated Power: 0.063W; Rated Voltage: N/A; Resistor Type: THICK FILM; Revision: R021; Status: Released; Texas Part Status: Under Review; Type: Resistor; Vendor: VISHAY; Vendor Part Number: CRCW04020000Z0ED; Vendor Part Status: Active
R351 = RESISTOR: RESISTOR, THICK FILM, 100k, -5%/+5%, 0.063W, 50V, -55DEGC/+155DEGC, 0402, SMD; Additional Datasheet URL: N/A; Budgetary Price: 0.014 EUR; Country of Origin: United States; Datasheet URL: https://www.vishay.com/docs/20035/dcrcwe3.pdf; Exclusive for Customers: TEXAS INSTRUMENTS NORWAY; Lead Time: 18; Mass: 0.00065g; Maximum Operating Temperature: +155DEGC; Maximum Temperature Coefficient: +200PPM/DEGC; Maximum Tolerance: +5%; Minimum Operating Temperature: -55DEGC; Minimum Temperature Coeficient: -200PPM/DEGC; Minimum Tolerance: -5%; Mounting Type: SMD; NOTEfied URL: https://notefied-dynamic-precision.com/NOTEfiedWebInterface/part/show?partNumber=01-22492; Notes: Standard item: Duplicate Reason: custom footprint for TEXAS INSTRUMENTS NORWAY.; PCB Package: 0402; Packing Size: 10000; Packing Type: Tape & Reel; Part Number: 01-22492; Part Type: Resistor|0402|STANDARD; REACH/SVHC Compliance: Compliant; REACH/SVHC Details: SVHC List Version Jun 20, 2016; REACH/SVHC Source: Material Declaration; REACH/SVHC Status: Unaffected; ROHS: Exempt; Rated Current: N/A; Rated Power: 0.063W; Rated Voltage: 50V; Resistor Type: THICK FILM; Revision: R014; Status: Released; Texas Part Status: Under Review; Type: Resistor; Vendor: VISHAY; Vendor Part Number: CRCW0402100KJNED; Vendor Part Status: Active
U1 = IC_RF_CC1311R1F32TRKPR_VQFN40: IC, MICROCONTROLLER, TEXAS INSTRUMENTS, CC1311R SIMPLE LINK HIGH-REFORMANCE SUB-1GHz WIRELESS MCU, 1.8V TO 3.8V, VQFN40-EP, SMD; ALT_SYMBOLS: QFNFC40P500X500X100-41A2L,QFNFC40P500X500X100-41A2M; Additional Datasheet URL: N/A; Datasheet URL: https://www.ti.com/; Exclusive for Customers: TEXAS INSTRUMENTS NORWAY; Frequency: 48MHz; Mass: N/A; Maximum Operating Temperature: +105DEGC; Minimum Operating Temperature: -40DEGC; Mounting Type: SMD; NOTEfied URL: https://notefied-dynamic-precision.com/NOTEfiedWebInterface/part/show?partNumber=18-36302; Notes: Preliminary item, please check if it apperas on the website.; PCB Package: VQFN40-EP; Packing Size: N/A; Packing Type: Missing Info; Part Number: 18-36302; Part Type: IC|MICROCONTROLLER|TEXAS INSTRUMENTS; REACH/SVHC Compliance: Missing Info; REACH/SVHC Details: N/A; REACH/SVHC Source: N/A; REACH/SVHC Status: Missing Info; ROHS: Compliant; Rated Voltage: 1.8V TO 3.8V; Revision: R002; Status: Released; Texas Part Status: Under Review; Type: IC; Vendor: TEXAS INSTRUMENTS; Vendor Part Status: Preliminary
Y1 = XTAL: CRYSTAL, RESONATOR, 32.768kHz, -40DEGC/+125DEGC, SMD; ALT_SYMBOLS: XTAL_TZ1166C_B2L,XTAL_TZ1166C_B2M; Additional Datasheet URL: N/A; Capacitance: 7pF; Datasheet URL: https://www.taisaw.com/en/product.php?pc=7; Exclusive for Customers: TEXAS INSTRUMENTS NORWAY; Mass: N/A; Maximum Operating Temperature: +125DEGC; Maximum Stability: N/A; Maximum Tolerance: +20PPM; Minimum Operating Temperature: -40DEGC; Minimum Stability: N/A; Minimum Tolerance: -20PPM; Mounting Type: SMD; NOTEfied URL: https://notefied-dynamic-precision.com/NOTEfiedWebInterface/part/show?partNumber=12-01495; Notes: Non-standard part/non-catalogue part. Created on the basis of documentation provided by the customer (Texas Instruments).; Packing Size: 3000; Packing Type: Tape & Reel; Part Number: 12-01495; Part Type: Crystal|RESONATOR; REACH/SVHC Compliance: Missing Info; REACH/SVHC Details: N/A; REACH/SVHC Source: N/A; REACH/SVHC Status: Missing Info; ROHS: Compliant; Revision: R003; Status: Released; Texas Part Status: Under Review; Type: Crystal; Vendor: TAI-SAW; Vendor Part Number: TZ1166C; Vendor Part Status: Active
Y2 = XTAL_4_V3: CRYSTAL, RESONATOR, 48MHz, -16PPM/+16PPM, -40DEGC/+105DEGC, SMD; ALT_SYMBOLS: OSCCC200X160X50-4A2L,OSCCC200X160X50-4A2M; Additional Datasheet URL: N/A; Capacitance: 7pF; Datasheet URL: https://www.taisaw.com/en/product.php?pc=7; Exclusive for Customers: TEXAS INSTRUMENTS NORWAY; Mass: 0.0057g; Maximum Operating Temperature: +105DEGC; Maximum Stability: +16PPM; Maximum Tolerance: +8PPM; Minimum Operating Temperature: -40DEGC; Minimum Stability: -16PPM; Minimum Tolerance: -8PPM; Mounting Type: SMD; NOTEfied URL: https://notefied-dynamic-precision.com/NOTEfiedWebInterface/part/show?partNumber=12-01494; Notes: Non-standard part/non-catalogue part. Created on the basis of documentation provided by the customer (Texas Instruments).; Packing Size: 3000; Packing Type: Tape & Reel; Part Number: 12-01494; Part Type: Crystal|RESONATOR; REACH/SVHC Compliance: Missing Info; REACH/SVHC Details: N/A; REACH/SVHC Source: N/A; REACH/SVHC Status: Missing Info; ROHS: Compliant; Revision: R002; Status: Released; Texas Part Status: Under Review; Type: Crystal; Vendor: TAI-SAW; Vendor Part Number: TZ2365C; Vendor Part Status: Active
Y3 = XTAL_GEN: CRYSTAL, OSCILLATOR, TCXO, 48MHz, -0.5PPM/+0.5PPM, 1.8V TO 3.3V, -40DEGC/+85DEGC, SMD; ALT_SYMBOLS: OSC_TG2016SBN_A2L,OSC_TG2016SBN_A2M; Additional Datasheet URL: http://www5.epsondevice.com/en/products/tcxo/tg2016sbn.html; Datasheet URL: https://support.epson.biz/td/api/doc_check.php?dl=brief_TG2016SBN&lang=en; Maximum Operating Temperature: +85DEGC; Maximum Stability: +0.5PPM; Minimum Operating Temperature: -40DEGC; Minimum Stability: -0.5PPM; Mounting Type: SMD; NOTEfied URL: https://notefied-dynamic-precision.com/NOTEfiedWebInterface/part/show?partNumber=12-01262; Part Number: 12-01262; Part Type: Crystal|OSCILLATOR|TCXO; REACH/SVHC Compliance: Compliant; REACH/SVHC Details: List Version Jan 12, 2017; REACH/SVHC Source: REACH Declaration; REACH/SVHC Status: Unaffected; ROHS: Compliant; Rated Voltage: 1.8V TO 3.3V; Revision: R012; Status: Released; Texas Part Status: Under Review; Type: Crystal; Vendor: EPSON; Vendor Part Number: TG2016SBN 48.000000MHz TCGNNA; Vendor Part Status: Active

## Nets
GND: C1.2 C11.2 C12.2 C13.1 C14.1 C21.1 C41.2 C51.2 C131.2 C221.2 C231.2 C331.2 C341.2 C342.2 C351.2 C441.2 C451.2 C461.2 C472.2 C473.2 C481.2 J1.2 J1.3 J1.4 J1.5 L15.2 P1.1 P1.19 P2.2 P2.20 U1.41(EGP) Y2.2(GND) Y2.4(GND) Y3.2(GND)
VDD_EB: FL1.2 P2.7 P2.9
VDDR: C331.1 C451.1 C481.1 L331.2 U1.37(VDDR_1/2) U1.40(VDDR_3/4)
VDDS: C1.1 C131.1 C221.1 C341.1 C342.1 C441.1 C472.1 FL1.1 R351.2 U1.13(VDDS2) U1.16(VDDS3) U1.26(VDDA1/2) U1.36(VDDA3_VDDS1) Y3.4(VDD)
DCDC_SW: L331.1 U1.25(DCDC_SW)
DIO_1: P1.5 U1.6(DIO_1)
DIO_2: P1.7 U1.7(DIO_2)
DIO_3: P1.9 U1.8(DIO_3)
DIO_4: P1.11 U1.9(DIO_4)
DIO_5: P1.13 U1.10(DIO_5)
DIO_6: P1.4 U1.11(DIO_6)
DIO_7: P1.2 U1.12(DIO_7)
DIO_8: P1.20 U1.14(DIO_8)
DIO_9: P1.18 U1.15(DIO_9)
DIO_10: P1.16 U1.20(DIO_10)
DIO_11: P1.14 U1.21(DIO_11)
DIO_12: P1.12 U1.22(DIO_12)
DIO_13: P1.15 U1.23(DIO_13)
DIO_14: P1.17 U1.24(DIO_14)
DIO_15: P1.6 U1.28(DIO_15)
DIO_16 / JTAG TDO: P2.19 U1.29(DIO_16)
DIO_17 / JTAG TDI: P2.17 U1.30(DIO_17)
DIO_18: P1.8 U1.31(DIO_18)
DIO_19: P1.10 U1.32(DIO_19)
DIO_20: P2.8 P2.12 U1.33(DIO_20)
DIO_21: P2.14 P2.18 U1.34(DIO_21)
DIO_22: P1.3 U1.35(DIO_22)
JTAG_TCK: P2.1 U1.19(JTAG_TCKC)
JTAG_TMS: P2.4 U1.18(JTAG_TMSC)
nRESET: C351.1 P2.15 R351.1 U1.27(nRESET)
N485531: J1.1 R11.1
N485535: A1.1(FEED/GND) L15.1 R13.1
N485643: C22.1 L11.2 L21.1 U1.2(SUB-1_GHZ_RF_N)
N485645: C11.1 L11.1 L12.1 U1.1(SUB-1_GHZ_RF_P)
N485661: C12.1 C22.2 L12.2 L13.1
N485675: C13.2 L13.2 L14.1
N485699: C231.1 U1.17(DCOUPL)
N485701: C41.1 U1.4(X32K_Q1) Y1.1
N485707: C51.1 U1.5(X32K_Q2) Y1.2
N485827: C14.2 C15.2 L14.2
N485893: C15.1 R11.2 R12.1
N485901: R12.2 R13.2
N485927: C21.2 L21.2 U1.3(RX_TX)
N485947: C461.1 U1.38(X24M_N) Y2.3
N499675: C471.2 C473.1 U1.39(X24M_P) Y2.1
N509134: C471.1 Y3.3(OUT)

Not connected (* = marked no-connect by the designer): FIDU1 1*; FIDU2 1*; FIDU3 1*; FIDU4 1*; FIDU5 1*; FIDU6 1*; P2 3* 5* 6* 10* 11* 13* 16*; Y3 1(NC)*

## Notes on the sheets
sheet 1
- VDDS Decoupling Capacitors
- VDDR Decoupling Capacitors
- Pin 13
- Pin 22
- Pin 44
- Pin 34
- Pin 45
- Pin 48
- Place L331 and C331 close to pin 33.
  Low inductance ground for C331
- Mount either R11 or R12
  to select SMA or PCB ant.
- Using external crystal load capacitors instead of internal:
  C461 and C473: 7.5 pF
- Using TCXO instead of crystal:
  Remove 48 MHz crystal (Y2) and solder TCXO (Y3) and C471.
  C471: 100 nF
- EM connector 1
- EM connector 2
sheet 2
- A0
  --------------------------------------------------------------------------------------------
  - Initial release revision. Based on CC1312REM-XD7793 Rev:C1
  - Changed C11 C22 from GRM1555C1H3R6CA01D to GJM1555C1H3R6CB01D
  - Changed C12 from GRM1555C1H2R7CA01D to GJM1555C1H2R7CB01D
  - Changed C13 from GRM1555C1H6R2CA01D to GJM1555C1H6R2CB01D
  - Changed C14 from GRM1555C1H3R0CA01D to GJM1555C1H3R0CB01D
  - Changed C15 C21 from GRM1555C1H101JA01D to GRT1555C1H101JA02D
  - Changed C41 C51 from GRM1555C1H120JA01D to GJM1555C1H120JB01D
  - Changed C231 from GRM155R61E105KA12D to GRM155C81C105KE11D
  - Changed C331 C341 from GRM188R60J226MEA0D to GRM188C80J226ME15D
  - Changed C461 C473 from GRM1555C1H7R5CA01D to GJM1555C1H7R5CB01D
  - Changed U1 from CC1312R1F3RGZR to CC1311R31T0RKPR
  - Changed Y1 from FC-135 32.7680KA-AG0 to TZ1166C
  - Changed Y2 from NX2016SA 48.000MHz EXS00A-CS05517 to TZ2365C
